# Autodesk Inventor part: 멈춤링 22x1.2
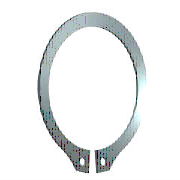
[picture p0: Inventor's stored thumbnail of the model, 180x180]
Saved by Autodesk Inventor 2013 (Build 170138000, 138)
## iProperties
IsCustomPart: 0
Created: 2015-11
Part Number: 멈춤링 22x1.2
Material: 스테인리스강
Description: 리테이닝 링(C형)
Document SubType Name: Modeling
Standard: KS B 1336
Designer: mdu
Standards Organization: KS
Language: ko-KR
Size Designation: 22 x 1.2
Categories: <MemberInstance><Categories><Category DisplayName="샤프트 부품" InternalName="7f7aeb1f-a693-4053-b835-cee3144e0d98" Mnemonic="SHFT"><Category DisplayName="써클립" Inter
Density: 1 g/cm^3
Author: mdu
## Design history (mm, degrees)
sketch "스케치1"
  geometry: L1 (-6, 0)-(6, 0) reference; L2 (0, 20.189)-(0, -80.536) reference; L3 (-48.09, 0)-(48.09, 0) reference; L4 (-0.5, -21.488)-(-0.5, -25.588); L5 (-0.5, -6.54)-(-0.5, -13.29); L6 (-2.795, 2.7)-(3.672, 2.7); L7 (0.5, -6.54)-(0.5, -13.29); L8 (0.5, -21.488)-(0.5, -25.588); C1 r 1 at (-2, -23.437); C2 r 1 at (2, -23.437); A1 r 10.5 centre (0, -11) between (0.5, -21.488) and (-0.5, -21.488); A2 r 13.025 centre (0, -10.325) between (5.149, -22.289) and (-5.149, -22.289); A3 r 14.597 centre (0, -11) between (-2.318, -25.411) and (-0.5, -25.588); A4 r 2 centre (-2, -23.437) between (-3.97, -23.781) and (-2.318, -25.411); A5 r 2 centre (-5.94, -24.126) between (-3.97, -23.781) and (-5.149, -22.289); A6 r 2 centre (5.94, -24.126) between (5.149, -22.289) and (3.97, -23.781); A7 r 2 centre (2, -23.437) between (2.318, -25.411) and (3.97, -23.781); A8 r 14.597 centre (0, -11) between (0.5, -25.588) and (2.318, -25.411)
  constraints: 16 point on circle, 12 end point, 10 centre point, 9 symmetric about line, 5 point on line, 4 tangent, 3 coincident, 2 horizontal, 1 perpendicular, 1 vertical, 5 other
  dimensions: "d0" = 21 diameter of A1 (= ND); "d1" = 4.1 distance of L4.end L4.start (= SRB2); "d6" = 0.5 distance between parallel lines of L2 L5 (= 0.25 x SD5); "d7" = 2.7 distance between parallel lines of L6 L3 (= SRB1); "d8" = 0.675 distance of A1.centre A2.centre (= 0.25 x SRB1); "d9" = 2 radius of A4 (= SD5); "d10" = 2 radius of A5 (= SD5); "d11" = 1.5 distance from line of L4 A4.centre (= 0.75 x SD5); "d12" = 2 diameter of C1 (= SD5); "d13" = 2 diameter of C2 (= SD5); "d14" = 11 distance from line of A1.centre L1 (= 0.5 x WD)
extrude "본체" new body sketch "스케치1" distance "d2" = 1.2 (= SD); taper "d3" = 0 deg
workaxis "Work Axis1"
workplane "Work Plane1"
body "Solid1"
other parameters: "WD" = 22 (= WDMIN) [user parameter; used in 1 equation term], "SD" = 1.2 [user parameter; used in 1 equation term], "SRB1" = 2.7 [user parameter; used in 2 equation terms], "ND" = 21 [user parameter; used in 1 equation term], "SRB2" = 4.1 [user parameter; used in 1 equation term], "SD5" = 2 [user parameter; used in 6 equation terms], "d15" = 0, "d16" = 0, "d17" = 0, "d41" = 0, "d42" = 0, "WDMIN" = 22 [user parameter; used in 1 equation term], "SD3" = 20.5 [user parameter], "WDMAX" = 24 [user parameter]
